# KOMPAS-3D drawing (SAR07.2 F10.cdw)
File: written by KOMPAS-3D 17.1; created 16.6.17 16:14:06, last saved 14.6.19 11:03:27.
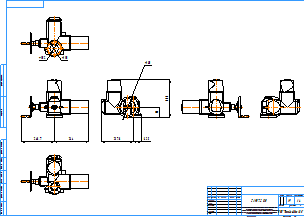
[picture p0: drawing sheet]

Sheet 1: A2, landscape

Title block, sheet 1: name: SAR07.2 F10; material: Сталь 20  ГОСТ 1050-88; mass: 19; sheets: 1; sheet format: A2; stored path: \\adlc.lan\data\АДЛ_ПКД\3D-модели\Поставщики\Сервоприводы AUMA\Электроприводы серии SA\KOMPAS 2D\SA 07.6 F10.cdw

Views: Спереди 1, Проекционный вид 2, Проекционный вид 3, Проекционный вид 4, Проекционный вид 6, Проекционный вид 5
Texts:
  Klimkovich
  ADL
  Рама для чертежей
  Лит-Масса-Масштаб
  Материал-Предприятие
  Масштаб
  Изм.
  Лист
  № докум.
  Подп.
  Дата
  Лит.
  Разраб.
  Пров.
  Т.контр.
  Листов
  Внимание! Данный продукт является объектом авторского права ООО «Торговый Дом АДЛ».
  Запрещается изменение, копирование, распространение
  (в том числе путем копирования на другие сайты и ресурсы в Интернете)
  или любое иное использование информации и объектов без предварительного
  согласия правообладателя (ООО «Торговый Дом АДЛ»).
  Н.контр.
  Утв.
  ООО "Торговый дом АДЛ"
  Изменение
  Номер документа
  Подпись
  Обозначение документа
  Наименование изделия
  Масса изделия по ГОСТ 2.109-73
  Порядковый номер листа
  Общее количество листов в документе
  Характер работы, выполненной лицом, подписавшим документ
  Наименование или индекс предприятия, выпускающего документ
  Инв. № подл.
  Подп. и дата
  Взам. инв. №
  Инв. № дубл.
  Инвентарный номер подлинника по ГОСТ 2.501-68
  Подпись принявшего подлинник в отдел технической документации
  Инвентарный номер подлинника, взамен которого выпущен данный подлинник
  Инвентарный номер дубликата по ГОСТ 2.502-68
  Подпись принявшего дубликат в отдел технической документации
  Справ. №
  Перв. примен.
  Обозначение документа, взамен или на основании которого выпущен данный документ
  Обозначение документа, в котором впервые записан данный документ
  Подпись лица, копировавшего чертеж
  Обозначение формата листа
  !Рама для чертежа
Dimensions and other numbers on the sheet: 160; 288; 62,5; 237,8; 78; 248,7; 264; 102; 110; 1:4; 1; 19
